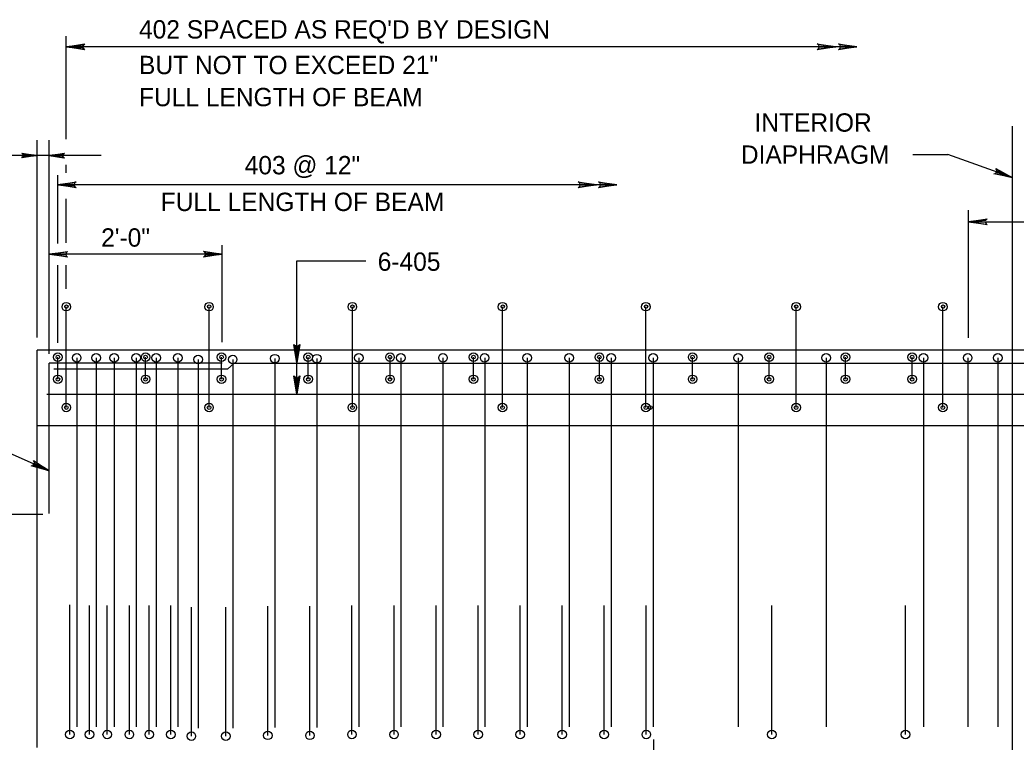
# Model space of a CAD drawing. Extents: x 637933 to 640019, y 298854 to 300042.
# Drawn here: x 638067.4 to 638230.3, y 299711.4 to 299829.5 of the extents above; entities that cross this region are included whole.
import ezdxf

# ---------------------------------------------------------------- set-up
doc = ezdxf.new("R2010")
doc.units = 0
doc.layers.add('1', color=7, linetype='Continuous')

msp = doc.modelspace()

# ---------------------------------------------------------------- linework, layer by layer
at = {"layer": '1'}
for p, q in [((638074.98, 299809.99), (638074.98, 299826.87)), ((638204.25, 299825.13), (638074.98, 299825.13)), ((638229.63, 299812.16), (638229.63, 299705.93)), ((638070.19, 299777.59), (638070.19, 299809.86)), ((638072.19, 299776.73), (638072.19, 299809.86)), ((638080.7, 299807.36), (638056.83, 299807.36)), ((638213.39, 299807.53), (638219.1, 299807.53)), ((638229.63, 299803.77), (638219.1, 299807.53)), ((638074.98, 299804.49), (638074.98, 299805.84)), ((638073.61, 299792.95), (638073.61, 299804.11)), ((638165.02, 299802.56), (638073.61, 299802.56)), ((638074.98, 299793.06), (638074.98, 299800.25)), ((638222.43, 299798.42), (638222.43, 299777.53)), ((638222.43, 299796.49), (638242.78, 299796.49)), ((638072.19, 299774.88), (638072.19, 299792.69)), ((638100.44, 299776.83), (638100.44, 299792.69)), ((638100.44, 299791.19), (638072.19, 299791.19)), ((638073.61, 299776.71), (638073.61, 299789.42)), ((638074.98, 299785.55), (638074.98, 299789.42)), ((638112.68, 299773.97), (638112.68, 299790.13)), ((638112.68, 299790.13), (638123.95, 299790.13)), ((638074.98, 299766.11), (638074.98, 299782.61)), ((638074.98, 299782.61), (638074.98, 299782.61)), ((638074.98, 299782.61), (638074.98, 299782.61)), ((638074.98, 299782.61), (638074.98, 299782.61)), ((638074.98, 299782.61), (638074.98, 299782.61)), ((638098.32, 299766.11), (638098.32, 299782.61)), ((638098.32, 299782.61), (638098.32, 299782.61)), ((638098.32, 299782.61), (638098.32, 299782.61)), ((638098.32, 299782.61), (638098.32, 299782.61)), ((638098.32, 299782.61), (638098.32, 299782.61)), ((638121.75, 299766.11), (638121.75, 299782.61)), ((638122.32, 299782.61), (638122.32, 299782.61)), ((638122.32, 299782.61), (638122.32, 299782.61)), ((638122.32, 299782.61), (638122.32, 299782.61)), ((638122.32, 299782.61), (638122.32, 299782.61)), ((638146.32, 299766.11), (638146.32, 299782.61)), ((638146.32, 299782.61), (638146.32, 299782.61)), ((638146.32, 299782.61), (638146.32, 299782.61)), ((638146.32, 299782.61), (638146.32, 299782.61)), ((638146.32, 299782.61), (638146.32, 299782.61)), ((638169.75, 299766.11), (638169.75, 299782.61)), ((638170.32, 299782.61), (638170.32, 299782.61)), ((638170.32, 299782.61), (638170.32, 299782.61)), ((638170.32, 299782.61), (638170.32, 299782.61)), ((638170.32, 299782.61), (638170.32, 299782.61)), ((638194.32, 299766.11), (638194.32, 299782.61)), ((638194.32, 299782.61), (638194.32, 299782.61)), ((638194.32, 299782.61), (638194.32, 299782.61)), ((638194.32, 299782.61), (638194.32, 299782.61)), ((638194.32, 299782.61), (638194.32, 299782.61)), ((638218.32, 299766.11), (638218.32, 299782.61)), ((638218.32, 299782.61), (638218.32, 299782.61)), ((638218.32, 299782.61), (638218.32, 299782.61)), ((638218.32, 299782.61), (638218.32, 299782.61)), ((638218.32, 299782.61), (638218.32, 299782.61)), ((638070.19, 299710.48), (638070.19, 299775.48)), ((638296.43, 299775.48), (638070.19, 299775.48)), ((638073.61, 299770.73), (638073.61, 299774.36)), ((638073.61, 299774.36), (638073.61, 299774.36)), ((638073.61, 299774.36), (638073.61, 299774.36)), ((638073.61, 299774.36), (638073.61, 299774.36)), ((638073.61, 299774.36), (638073.61, 299774.36)), ((638076.68, 299774.23), (638076.68, 299774.23)), ((638076.68, 299774.23), (638076.68, 299774.23)), ((638076.68, 299774.23), (638076.68, 299774.23)), ((638076.68, 299774.23), (638076.68, 299774.23)), ((638076.68, 299774.23), (638076.68, 299713.89)), ((638079.88, 299774.23), (638079.88, 299774.23)), ((638079.88, 299774.23), (638079.88, 299774.23)), ((638079.88, 299774.23), (638079.88, 299774.23)), ((638079.88, 299774.23), (638079.88, 299774.23)), ((638079.88, 299774.23), (638079.88, 299713.89)), ((638082.8, 299774.23), (638082.8, 299774.23)), ((638082.8, 299774.23), (638082.8, 299774.23)), ((638082.8, 299774.23), (638082.8, 299774.23)), ((638082.8, 299774.23), (638082.8, 299774.23)), ((638082.8, 299774.23), (638082.8, 299713.89)), ((638086.41, 299774.23), (638086.41, 299774.23)), ((638086.41, 299774.23), (638086.41, 299774.23)), ((638086.41, 299774.23), (638086.41, 299774.23)), ((638086.41, 299774.23), (638086.41, 299774.23)), ((638086.41, 299774.23), (638086.41, 299713.89)), ((638087.95, 299770.73), (638087.95, 299774.36)), ((638087.95, 299774.36), (638087.95, 299774.36)), ((638087.95, 299774.36), (638087.95, 299774.36)), ((638087.95, 299774.36), (638087.95, 299774.36)), ((638087.95, 299774.36), (638087.95, 299774.36)), ((638089.68, 299774.23), (638089.68, 299774.23)), ((638089.68, 299774.23), (638089.68, 299774.23)), ((638089.68, 299774.23), (638089.68, 299774.23)), ((638089.68, 299774.23), (638089.68, 299774.23)), ((638089.68, 299774.23), (638089.68, 299713.89)), ((638093.22, 299774.23), (638093.22, 299774.23)), ((638093.22, 299774.23), (638093.22, 299774.23)), ((638093.22, 299774.23), (638093.22, 299774.23)), ((638093.22, 299774.23), (638093.22, 299774.23)), ((638093.22, 299774.23), (638093.22, 299713.89)), ((638100.36, 299770.73), (638100.36, 299774.36)), ((638100.36, 299774.36), (638100.36, 299774.36)), ((638100.36, 299774.36), (638100.36, 299774.36)), ((638100.36, 299774.36), (638100.36, 299774.36)), ((638100.36, 299774.36), (638100.36, 299774.36)), ((638109.07, 299774.11), (638109.07, 299774.11)), ((638109.07, 299774.11), (638109.07, 299774.11)), ((638109.07, 299774.11), (638109.07, 299774.11)), ((638109.07, 299774.11), (638109.07, 299774.11)), ((638109.07, 299774.11), (638109.07, 299713.77)), ((638114.53, 299770.73), (638114.53, 299774.36)), ((638114.53, 299774.36), (638114.53, 299774.36)), ((638114.53, 299774.36), (638114.53, 299774.36)), ((638114.53, 299774.36), (638114.53, 299774.36)), ((638114.53, 299774.36), (638114.53, 299774.36)), ((638115.94, 299774.11), (638115.94, 299774.11)), ((638115.94, 299774.11), (638115.94, 299774.11)), ((638115.94, 299774.11), (638115.94, 299774.11)), ((638115.94, 299774.11), (638115.94, 299774.11)), ((638115.94, 299774.11), (638115.94, 299713.77)), ((638122.82, 299774.23), (638122.82, 299774.23)), ((638122.82, 299774.23), (638122.82, 299774.23)), ((638122.82, 299774.23), (638122.82, 299774.23)), ((638122.82, 299774.23), (638122.82, 299774.23)), ((638122.82, 299774.23), (638122.82, 299713.89)), ((638127.91, 299770.73), (638127.91, 299774.36)), ((638127.91, 299774.36), (638127.91, 299774.36)), ((638127.91, 299774.36), (638127.91, 299774.36)), ((638127.91, 299774.36), (638127.91, 299774.36)), ((638127.91, 299774.36), (638127.91, 299774.36)), ((638129.69, 299774.23), (638129.69, 299774.23)), ((638129.69, 299774.23), (638129.69, 299774.23)), ((638129.69, 299774.23), (638129.69, 299774.23)), ((638129.69, 299774.23), (638129.69, 299774.23)), ((638129.69, 299774.23), (638129.69, 299713.89)), ((638136.57, 299774.23), (638136.57, 299774.23)), ((638136.57, 299774.23), (638136.57, 299774.23)), ((638136.57, 299774.23), (638136.57, 299774.23)), ((638136.57, 299774.23), (638136.57, 299774.23)), ((638136.57, 299774.23), (638136.57, 299713.89)), ((638141.55, 299770.73), (638141.55, 299774.36)), ((638141.55, 299774.36), (638141.55, 299774.36)), ((638141.55, 299774.36), (638141.55, 299774.36)), ((638141.55, 299774.36), (638141.55, 299774.36)), ((638141.55, 299774.36), (638141.55, 299774.36)), ((638143.44, 299774.23), (638143.44, 299774.23)), ((638143.44, 299774.23), (638143.44, 299774.23)), ((638143.44, 299774.23), (638143.44, 299774.23)), ((638143.44, 299774.23), (638143.44, 299774.23)), ((638143.44, 299774.23), (638143.44, 299713.89)), ((638149.59, 299774.23), (638149.59, 299774.23)), ((638149.68, 299774.23), (638149.68, 299774.23)), ((638149.87, 299774.23), (638149.87, 299774.23)), ((638150.32, 299774.23), (638150.32, 299774.23)), ((638150.32, 299774.23), (638150.32, 299774.23)), ((638150.32, 299774.23), (638150.32, 299774.23)), ((638150.32, 299774.23), (638150.32, 299774.23)), ((638150.32, 299774.23), (638150.32, 299713.89)), ((638157.19, 299774.23), (638157.19, 299774.23)), ((638157.19, 299774.23), (638157.19, 299774.23)), ((638157.19, 299774.23), (638157.19, 299774.23)), ((638157.19, 299774.23), (638157.19, 299774.23)), ((638157.19, 299774.23), (638157.19, 299713.89)), ((638162.14, 299770.73), (638162.14, 299774.36)), ((638162.14, 299774.36), (638162.14, 299774.36)), ((638162.14, 299774.36), (638162.14, 299774.36)), ((638162.14, 299774.36), (638162.14, 299774.36)), ((638162.14, 299774.36), (638162.14, 299774.36)), ((638164.07, 299774.23), (638164.07, 299774.23)), ((638164.07, 299774.23), (638164.07, 299774.23)), ((638164.07, 299774.23), (638164.07, 299774.23)), ((638164.07, 299774.23), (638164.07, 299774.23)), ((638164.07, 299774.23), (638164.07, 299713.89)), ((638170.94, 299774.23), (638170.94, 299774.23)), ((638170.94, 299774.23), (638170.94, 299774.23)), ((638170.94, 299774.23), (638170.94, 299774.23)), ((638170.94, 299774.23), (638170.94, 299774.23)), ((638170.94, 299774.23), (638170.94, 299713.89)), ((638177.39, 299770.73), (638177.39, 299774.36)), ((638177.39, 299774.36), (638177.39, 299774.36)), ((638177.39, 299774.36), (638177.39, 299774.36)), ((638177.39, 299774.36), (638177.39, 299774.36)), ((638177.39, 299774.36), (638177.39, 299774.36)), ((638184.84, 299774.23), (638184.84, 299713.89)), ((638184.84, 299774.23), (638184.84, 299774.23)), ((638184.84, 299774.23), (638184.84, 299774.23)), ((638184.84, 299774.23), (638184.84, 299774.23)), ((638184.84, 299774.23), (638184.84, 299774.23)), ((638189.89, 299770.73), (638189.89, 299774.36)), ((638189.89, 299774.36), (638189.89, 299774.36)), ((638189.89, 299774.36), (638189.89, 299774.36)), ((638189.89, 299774.36), (638189.89, 299774.36)), ((638189.89, 299774.36), (638189.89, 299774.36)), ((638199.23, 299774.23), (638199.23, 299713.89)), ((638199.23, 299774.23), (638199.23, 299774.23)), ((638199.23, 299774.23), (638199.23, 299774.23)), ((638199.23, 299774.23), (638199.23, 299774.23)), ((638199.23, 299774.23), (638199.23, 299774.23)), ((638202.39, 299770.73), (638202.39, 299774.36)), ((638202.39, 299774.36), (638202.39, 299774.36)), ((638202.39, 299774.36), (638202.39, 299774.36)), ((638202.39, 299774.36), (638202.39, 299774.36)), ((638202.39, 299774.36), (638202.39, 299774.36)), ((638213.28, 299770.73), (638213.28, 299774.36)), ((638213.28, 299774.36), (638213.28, 299774.36)), ((638213.28, 299774.36), (638213.28, 299774.36)), ((638213.28, 299774.36), (638213.28, 299774.36)), ((638213.28, 299774.36), (638213.28, 299774.36)), ((638214.89, 299774.36), (638214.89, 299774.36)), ((638214.89, 299774.36), (638214.89, 299774.36)), ((638214.89, 299774.36), (638214.89, 299774.36)), ((638215.14, 299774.23), (638215.14, 299713.89)), ((638215.14, 299774.23), (638215.14, 299774.23)), ((638215.14, 299774.23), (638215.14, 299774.23)), ((638215.14, 299774.23), (638215.14, 299774.23)), ((638215.14, 299774.23), (638215.14, 299774.23)), ((638222.37, 299774.23), (638222.37, 299713.89)), ((638222.37, 299774.23), (638222.37, 299774.23)), ((638222.37, 299774.23), (638222.37, 299774.23)), ((638222.37, 299774.23), (638222.37, 299774.23)), ((638222.37, 299774.23), (638222.37, 299774.23)), ((638227.29, 299774.23), (638227.29, 299713.89)), ((638227.29, 299774.23), (638227.29, 299774.23)), ((638227.29, 299774.23), (638227.29, 299774.23)), ((638227.29, 299774.23), (638227.29, 299774.23)), ((638227.29, 299774.23), (638227.29, 299774.23)), ((638072.19, 299748.77), (638072.19, 299773.38)), ((638100.44, 299773.38), (638072.19, 299773.38)), ((638096.55, 299773.98), (638096.55, 299773.98)), ((638096.55, 299773.98), (638096.55, 299773.98)), ((638096.55, 299773.98), (638096.55, 299773.98)), ((638096.55, 299773.98), (638096.55, 299773.98)), ((638096.55, 299773.98), (638096.55, 299713.64)), ((638102.44, 299773.38), (638101.32, 299772.38)), ((638102.19, 299773.98), (638102.19, 299773.98)), ((638102.19, 299773.98), (638102.19, 299773.98)), ((638102.19, 299773.98), (638102.19, 299773.98)), ((638102.19, 299773.98), (638102.19, 299773.98)), ((638102.19, 299773.98), (638102.19, 299713.64)), ((638102.44, 299773.38), (638296.31, 299773.38)), ((638112.68, 299768.28), (638112.68, 299773.97)), ((638101.32, 299772.38), (638072.94, 299772.38)), ((638073.61, 299770.73), (638073.61, 299770.73)), ((638073.61, 299770.73), (638073.61, 299770.73)), ((638073.61, 299770.73), (638073.61, 299770.73)), ((638073.61, 299770.73), (638073.61, 299770.73)), ((638087.95, 299770.73), (638087.95, 299770.73)), ((638087.95, 299770.73), (638087.95, 299770.73)), ((638087.95, 299770.73), (638087.95, 299770.73)), ((638087.95, 299770.73), (638087.95, 299770.73)), ((638100.36, 299770.73), (638100.36, 299770.73)), ((638100.36, 299770.73), (638100.36, 299770.73)), ((638100.36, 299770.73), (638100.36, 299770.73)), ((638100.36, 299770.73), (638100.36, 299770.73)), ((638114.53, 299770.73), (638114.53, 299770.73)), ((638114.53, 299770.73), (638114.53, 299770.73)), ((638114.53, 299770.73), (638114.53, 299770.73)), ((638114.53, 299770.73), (638114.53, 299770.73)), ((638127.91, 299770.73), (638127.91, 299770.73)), ((638127.91, 299770.73), (638127.91, 299770.73)), ((638127.91, 299770.73), (638127.91, 299770.73)), ((638127.91, 299770.73), (638127.91, 299770.73)), ((638141.55, 299770.73), (638141.55, 299770.73)), ((638141.55, 299770.73), (638141.55, 299770.73)), ((638141.55, 299770.73), (638141.55, 299770.73)), ((638141.55, 299770.73), (638141.55, 299770.73)), ((638162.14, 299770.73), (638162.14, 299770.73)), ((638162.14, 299770.73), (638162.14, 299770.73)), ((638162.14, 299770.73), (638162.14, 299770.73)), ((638162.14, 299770.73), (638162.14, 299770.73)), ((638177.39, 299770.73), (638177.39, 299770.73)), ((638177.39, 299770.73), (638177.39, 299770.73)), ((638177.39, 299770.73), (638177.39, 299770.73)), ((638177.39, 299770.73), (638177.39, 299770.73)), ((638189.89, 299770.73), (638189.89, 299770.73)), ((638189.89, 299770.73), (638189.89, 299770.73)), ((638189.89, 299770.73), (638189.89, 299770.73)), ((638189.89, 299770.73), (638189.89, 299770.73)), ((638202.39, 299770.73), (638202.39, 299770.73)), ((638202.39, 299770.73), (638202.39, 299770.73)), ((638202.39, 299770.73), (638202.39, 299770.73)), ((638202.39, 299770.73), (638202.39, 299770.73)), ((638202.39, 299770.49), (638202.39, 299770.49)), ((638213.28, 299770.73), (638213.28, 299770.73)), ((638213.28, 299770.73), (638213.28, 299770.73)), ((638213.28, 299770.73), (638213.28, 299770.73)), ((638213.28, 299770.73), (638213.28, 299770.73)), ((638213.28, 299770.49), (638213.28, 299770.49)), ((638295.92, 299768.23), (638071.79, 299768.23)), ((638074.98, 299766.11), (638074.98, 299766.11)), ((638074.98, 299766.11), (638074.98, 299766.11)), ((638074.98, 299766.11), (638074.98, 299766.11)), ((638074.98, 299766.11), (638074.98, 299766.11)), ((638098.32, 299766.11), (638098.32, 299766.11)), ((638098.32, 299766.11), (638098.32, 299766.11)), ((638098.32, 299766.11), (638098.32, 299766.11)), ((638098.32, 299766.11), (638098.32, 299766.11)), ((638122.32, 299766.11), (638122.32, 299766.11)), ((638122.32, 299766.11), (638122.32, 299766.11)), ((638122.32, 299766.11), (638122.32, 299766.11)), ((638122.32, 299766.11), (638122.32, 299766.11)), ((638146.32, 299766.11), (638146.32, 299766.11)), ((638146.32, 299766.11), (638146.32, 299766.11)), ((638146.32, 299766.11), (638146.32, 299766.11)), ((638146.32, 299766.11), (638146.32, 299766.11)), ((638170.32, 299766.11), (638170.32, 299766.11)), ((638170.32, 299766.11), (638170.32, 299766.11)), ((638170.32, 299766.11), (638170.32, 299766.11)), ((638170.32, 299766.11), (638170.32, 299766.11)), ((638170.44, 299766.11), (638170.44, 299766.11)), ((638170.44, 299766.11), (638170.44, 299766.11)), ((638170.44, 299766.11), (638170.44, 299766.11)), ((638170.44, 299766.11), (638170.44, 299766.11)), ((638194.32, 299766.11), (638194.32, 299766.11)), ((638194.32, 299766.11), (638194.32, 299766.11)), ((638194.32, 299766.11), (638194.32, 299766.11)), ((638194.32, 299766.11), (638194.32, 299766.11)), ((638218.32, 299766.11), (638218.32, 299766.11)), ((638218.32, 299766.11), (638218.32, 299766.11)), ((638218.32, 299766.11), (638218.32, 299766.11)), ((638218.32, 299766.11), (638218.32, 299766.11)), ((638295.4, 299763.11), (638070.19, 299763.11)), ((638072.19, 299755.78), (638060.98, 299760.7)), ((638071.13, 299748.61), (638055.2, 299748.61)), ((638075.55, 299712.61), (638075.55, 299733.86)), ((638078.76, 299712.61), (638078.76, 299733.73)), ((638081.68, 299712.61), (638081.68, 299733.73)), ((638085.29, 299712.61), (638085.29, 299733.73)), ((638088.55, 299712.61), (638088.55, 299733.73)), ((638092.09, 299712.61), (638092.09, 299733.73)), ((638095.43, 299712.36), (638095.43, 299733.48)), ((638101.07, 299712.36), (638101.07, 299733.48)), ((638107.94, 299712.48), (638107.94, 299733.61)), ((638114.82, 299712.48), (638114.82, 299733.61)), ((638121.69, 299712.61), (638121.69, 299733.73)), ((638128.57, 299712.61), (638128.57, 299733.73)), ((638135.44, 299712.61), (638135.44, 299733.73)), ((638142.32, 299712.61), (638142.32, 299733.73)), ((638149.19, 299712.61), (638149.19, 299733.73)), ((638156.07, 299712.61), (638156.07, 299733.73)), ((638162.94, 299712.61), (638162.94, 299733.73)), ((638169.82, 299712.61), (638169.82, 299733.73)), ((638190.33, 299712.61), (638190.33, 299733.73)), ((638212.19, 299712.61), (638212.19, 299733.73)), ((638212.19, 299712.61), (638212.19, 299712.61)), ((638212.19, 299712.61), (638212.19, 299712.61)), ((638212.19, 299712.61), (638212.19, 299712.61)), ((638171.07, 299703.13), (638171.07, 299711.8))]:
    msp.add_line(p, q, dxfattribs=at)
for points in [[(638077.83, 299824.77), (638077.72, 299824.98), (638074.98, 299825.13), (638077.83, 299824.77), (638077.98, 299824.65), (638074.98, 299825.13), (638077.72, 299825.27), (638077.82, 299825.47), (638074.98, 299825.13), (638077.98, 299825.61), (638077.82, 299825.47)], [(638197.93, 299825.49), (638198.03, 299825.28), (638200.78, 299825.13), (638197.93, 299825.49), (638197.78, 299825.61), (638200.78, 299825.13), (638198.03, 299824.99), (638197.93, 299824.79), (638200.78, 299825.13), (638197.78, 299824.65), (638197.93, 299824.79)], [(638201.4, 299825.49), (638201.5, 299825.28), (638204.25, 299825.13), (638201.4, 299825.49), (638201.25, 299825.61), (638204.25, 299825.13), (638201.51, 299824.99), (638201.41, 299824.79), (638204.25, 299825.13), (638201.25, 299824.65), (638201.41, 299824.79)], [(638067.82, 299807.61), (638067.94, 299807.48), (638070.19, 299807.36), (638067.82, 299807.61), (638067.69, 299807.73), (638070.19, 299807.36), (638067.94, 299807.23), (638067.82, 299807.11), (638070.19, 299807.36), (638067.69, 299806.98), (638067.82, 299807.11)], [(638074.57, 299806.98), (638074.44, 299807.23), (638072.19, 299807.36), (638074.57, 299806.98), (638074.69, 299806.98), (638072.19, 299807.36), (638074.44, 299807.48), (638074.57, 299807.61), (638072.19, 299807.36), (638074.69, 299807.73), (638074.57, 299807.61)], [(638227.06, 299805.07), (638227.09, 299804.84), (638229.63, 299803.77), (638227.06, 299805.07), (638226.97, 299805.23), (638229.63, 299803.77), (638227, 299804.56), (638226.84, 299804.41), (638229.63, 299803.77), (638226.64, 299804.33), (638226.84, 299804.41)], [(638076.43, 299802.2), (638076.32, 299802.4), (638073.57, 299802.56), (638076.43, 299802.2), (638076.57, 299802.07), (638073.57, 299802.56), (638076.32, 299802.69), (638076.42, 299802.9), (638073.57, 299802.56), (638076.57, 299803.03), (638076.42, 299802.9)], [(638158.82, 299802.92), (638158.93, 299802.71), (638161.68, 299802.56), (638158.82, 299802.92), (638158.68, 299803.04), (638161.68, 299802.56), (638158.93, 299802.42), (638158.83, 299802.22), (638161.68, 299802.56), (638158.68, 299802.08), (638158.83, 299802.22)], [(638162.17, 299802.92), (638162.27, 299802.71), (638165.02, 299802.56), (638162.17, 299802.92), (638162.02, 299803.04), (638165.02, 299802.56), (638162.28, 299802.42), (638162.18, 299802.22), (638165.02, 299802.56), (638162.02, 299802.08), (638162.18, 299802.22)], [(638225.43, 299796.12), (638225.31, 299796.37), (638222.43, 299796.49), (638225.43, 299796.12), (638225.56, 299795.99), (638222.43, 299796.49), (638225.31, 299796.74), (638225.43, 299796.87), (638222.43, 299796.49), (638225.56, 299796.99), (638225.43, 299796.87)], [(638075.05, 299790.83), (638074.94, 299791.03), (638072.19, 299791.19), (638075.05, 299790.83), (638075.19, 299790.7), (638072.19, 299791.19), (638074.94, 299791.32), (638075.04, 299791.53), (638072.19, 299791.19), (638075.19, 299791.66), (638075.04, 299791.53)], [(638097.59, 299791.54), (638097.7, 299791.34), (638100.44, 299791.19), (638097.59, 299791.54), (638097.44, 299791.67), (638100.44, 299791.19), (638097.7, 299791.05), (638097.6, 299790.85), (638100.44, 299791.19), (638097.44, 299790.71), (638097.6, 299790.85)], [(638113.04, 299776.29), (638112.84, 299776.18), (638112.68, 299773.44), (638113.04, 299776.29), (638113.17, 299776.44), (638112.68, 299773.44), (638112.55, 299776.18), (638112.34, 299776.28), (638112.68, 299773.44), (638112.21, 299776.44), (638112.34, 299776.28)], [(638113.04, 299771.14), (638112.84, 299771.03), (638112.68, 299768.28), (638113.04, 299771.14), (638113.17, 299771.28), (638112.68, 299768.28), (638112.55, 299771.03), (638112.34, 299771.13), (638112.68, 299768.28), (638112.21, 299771.28), (638112.34, 299771.13)], [(638069.72, 299757.26), (638069.74, 299757.03), (638072.19, 299755.78), (638069.72, 299757.26), (638069.64, 299757.43), (638072.19, 299755.78), (638069.63, 299756.76), (638069.45, 299756.61), (638072.19, 299755.78), (638069.26, 299756.55), (638069.45, 299756.61)]]:
    msp.add_lwpolyline(points, dxfattribs=at)
for centre, radius in [((638074.98, 299782.61), 0.7), ((638074.99, 299782.63), 0.274), ((638098.32, 299782.61), 0.7), ((638098.34, 299782.63), 0.274), ((638121.75, 299782.61), 0.7), ((638121.77, 299782.63), 0.274), ((638146.32, 299782.61), 0.7), ((638146.34, 299782.63), 0.274), ((638169.75, 299782.61), 0.7), ((638169.77, 299782.63), 0.274), ((638194.32, 299782.61), 0.7), ((638194.34, 299782.63), 0.274), ((638218.32, 299782.61), 0.7), ((638218.34, 299782.63), 0.274), ((638073.61, 299774.36), 0.7), ((638073.61, 299774.36), 0.3), ((638076.68, 299774.23), 0.7), ((638079.88, 299774.23), 0.7), ((638082.8, 299774.23), 0.7), ((638086.41, 299774.23), 0.7), ((638087.95, 299774.36), 0.7), ((638087.95, 299774.36), 0.3), ((638089.68, 299774.23), 0.7), ((638093.22, 299774.23), 0.7), ((638096.55, 299773.98), 0.7), ((638100.36, 299774.36), 0.7), ((638100.36, 299774.36), 0.3), ((638102.19, 299773.98), 0.7), ((638109.07, 299774.11), 0.7), ((638114.53, 299774.36), 0.7), ((638114.53, 299774.36), 0.3), ((638115.94, 299774.11), 0.7), ((638122.82, 299774.23), 0.7), ((638127.91, 299774.36), 0.7), ((638127.91, 299774.36), 0.3), ((638129.69, 299774.23), 0.7), ((638136.57, 299774.23), 0.7), ((638141.55, 299774.36), 0.7), ((638141.55, 299774.36), 0.3), ((638143.38, 299774.23), 0.7), ((638150.32, 299774.23), 0.7), ((638157.19, 299774.23), 0.7), ((638162.14, 299774.36), 0.7), ((638162.14, 299774.36), 0.3), ((638164.07, 299774.23), 0.7), ((638170.94, 299774.23), 0.7), ((638177.39, 299774.36), 0.7), ((638177.39, 299774.36), 0.3), ((638184.84, 299774.23), 0.7), ((638189.89, 299774.36), 0.7), ((638189.89, 299774.36), 0.3), ((638199.23, 299774.23), 0.7), ((638202.39, 299774.36), 0.7), ((638202.39, 299774.36), 0.3), ((638213.28, 299774.36), 0.7), ((638213.28, 299774.36), 0.3), ((638215.14, 299774.23), 0.7), ((638222.37, 299774.23), 0.7), ((638227.29, 299774.23), 0.7), ((638073.61, 299770.73), 0.7), ((638073.61, 299770.73), 0.3), ((638087.95, 299770.73), 0.7), ((638087.95, 299770.73), 0.3), ((638100.36, 299770.73), 0.7), ((638100.36, 299770.73), 0.3), ((638114.53, 299770.73), 0.7), ((638114.53, 299770.73), 0.3), ((638127.91, 299770.73), 0.7), ((638127.91, 299770.73), 0.3), ((638141.55, 299770.73), 0.7), ((638141.55, 299770.73), 0.3), ((638162.14, 299770.73), 0.7), ((638162.14, 299770.73), 0.3), ((638177.39, 299770.73), 0.7), ((638177.39, 299770.73), 0.3), ((638189.89, 299770.73), 0.7), ((638189.89, 299770.73), 0.3), ((638202.39, 299770.73), 0.7), ((638202.39, 299770.73), 0.3), ((638213.28, 299770.73), 0.7), ((638213.28, 299770.73), 0.3), ((638074.98, 299766.11), 0.7), ((638074.98, 299766.11), 0.3), ((638098.32, 299766.11), 0.7), ((638098.32, 299766.11), 0.3), ((638121.75, 299766.11), 0.7), ((638121.76, 299766.11), 0.3), ((638146.32, 299766.11), 0.7), ((638146.32, 299766.11), 0.3), ((638169.75, 299766.11), 0.7), ((638169.76, 299766.11), 0.3), ((638170.45, 299766.11), 0.3), ((638194.32, 299766.11), 0.7), ((638194.32, 299766.11), 0.3), ((638218.32, 299766.11), 0.7), ((638218.32, 299766.11), 0.3), ((638075.55, 299712.61), 0.7), ((638078.76, 299712.61), 0.7), ((638081.68, 299712.61), 0.7), ((638085.29, 299712.61), 0.7), ((638088.55, 299712.61), 0.7), ((638092.09, 299712.61), 0.7), ((638095.43, 299712.36), 0.7), ((638101.07, 299712.36), 0.7), ((638107.94, 299712.48), 0.7), ((638114.82, 299712.48), 0.7), ((638121.69, 299712.61), 0.7), ((638128.57, 299712.61), 0.7), ((638135.44, 299712.61), 0.7), ((638142.32, 299712.61), 0.7), ((638149.19, 299712.61), 0.7), ((638156.07, 299712.61), 0.7), ((638162.94, 299712.61), 0.7), ((638169.82, 299712.61), 0.7), ((638190.33, 299712.61), 0.7), ((638212.19, 299712.61), 0.7)]:
    msp.add_circle(centre, radius, dxfattribs=at)

# ---------------------------------------------------------------- texts
for s, p in [("402 SPACED AS REQ'D BY DESIGN", (638086.87, 299826.48)), ('BUT NOT TO EXCEED 21"', (638086.87, 299820.65)), ('FULL LENGTH OF BEAM', (638086.87, 299815.4)), ('  INTERIOR', (638185.28, 299811.24)), ('DIAPHRAGM', (638185.28, 299805.99)), ('403 @ 12"', (638104.15, 299804.26)), ('FULL LENGTH OF BEAM', (638090.42, 299798.26)), ('2\'-0"', (638080.68, 299792.43)), ('6-405', (638125.9, 299788.48))]:
    msp.add_text(s, height=3, dxfattribs=at).set_placement(p)

doc.saveas('drawing.dxf')
